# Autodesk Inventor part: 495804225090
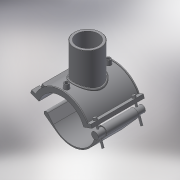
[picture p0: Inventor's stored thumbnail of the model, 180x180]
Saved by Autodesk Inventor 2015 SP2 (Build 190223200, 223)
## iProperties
Created: 2017-07
Part Number: 495804225090
Material: Generic
Description: PLASSON BRANCH SADDLE 225-90
Document SubType Name: Modeling
Designer: KIM
Density: 1 g/cm^3
Appearance: Default
Author: KIM
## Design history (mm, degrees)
derived "495804.ipt"
feature "Solid1::495804.ipt"
feature "Solid2::495804.ipt"
tag "TaggingFeature1"
body "Solid1"
body "Solid2"
other parameters: "d0" = 225, "d2" = 295.1, "d3" = 56.25, "d4" = 176, "d5" = 0, "d6" = 0.1, "d8" = 0, "d19" = 6, "d20" = 6, "d21" = 105.6, "d23" = 0, "d24" = 52.8, "d26" = 0, "d27" = 3, "d28" = 3, "d29" = 3, "d30" = 75, "d31" = 6, "d32" = 0, "d33" = 0, "d34" = 0.6, "d40" = 132.6, "d41" = 99, "d43" = 0, "d45" = 0, "d47" = 232.5, "d50" = 0, "d70" = 15, "d72" = 0, "d73" = 6, "d75" = 5, "d76" = 0, "d77" = 11.25, "d78" = 142.5, "d79" = 15, "d80" = 70.4, "d82" = 5 deg, "d84" = 4, "d85" = 14, "d86" = 0, "d87" = 3, "d88" = 0, "d89" = 1, "d90" = 1, "d91" = 140.8, "d92" = 0, "d93" = 0.5, "d94" = 118.42105, "d96" = 260.1, "d97" = 3.52, "d98" = 0, "d102" = 2.7, "d103" = 72, "d105" = 0, "d109" = -35, "d117" = 0.9, "d120" = 140 deg, "d121" = 24.228, "d122" = 20 deg, "d124" = 153, "d126" = 0, "d143" = 236.25, "d150" = 40.5, "d159" = 6, "d161" = 5.625, "d162" = 105.6, "d163" = 0, "d167" = 45, "d168" = 115.90909, "d173" = 1, "d175" = 112.5, "d176" = 20 deg, "d177" = 15.75, "d180" = 0, "d185" = 57.2, "d186" = 57.2, "d187" = 127.5, "d188" = 9, "d189" = 15.75, "d190" = 0, "d191" = 191.25, "d200" = 15, "d202" = 0, "d216" = 158.4, "d217" = 0, "d221" = 65.12, "d222" = 15.75, "d223" = 9.45, "d224" = 112.5, "d225" = 9.45, "d227" = 32.4, "d230" = 137.25, "d236" = 20 deg, "d237" = 134.5, "d238" = 20 deg, "d239" = 15.75, "d_" = 225, "B_" = 227, "H_" = 105, "L_" = 176, "d_t" = 6, "d1" = 255, "d148" = 5.625, "d160" = 5.625
